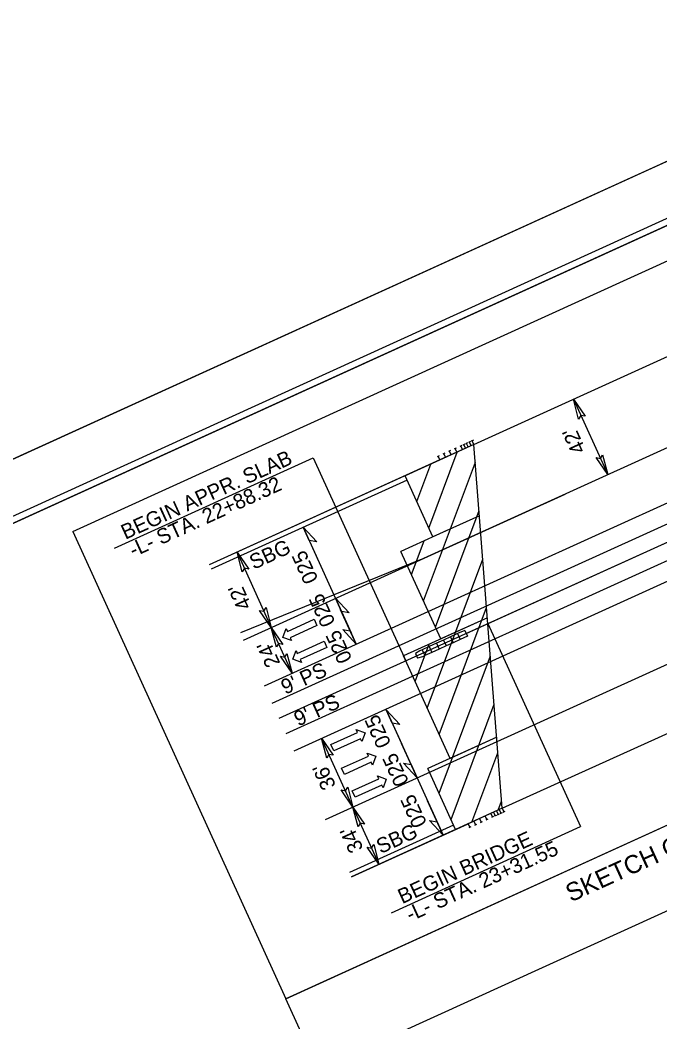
# Model space of a CAD drawing. Extents: x 2247864 to 2249896, y 662531 to 664296.
# Drawn here: x 2248640.5 to 2248887, y 663642.7 to 664028.8 of the extents above; entities that cross this region are included whole.
import ezdxf

# ---------------------------------------------------------------- set-up
doc = ezdxf.new("R2010")
doc.units = 0
for name, color, linetype in [('Prop Approach Slab', 7, 'Continuous'), ('Prop Approach Slab Hatching', 7, 'Continuous'), ('Prop Conc Barrier', 7, 'Continuous'), ('Prop Conc Shoulder Berm Gutter', 7, 'Continuous'), ('Prop Dimension', 7, 'Continuous'), ('Prop Dimension Text', 7, 'Continuous'), ('Prop EOT', 7, 'Continuous'), ('Prop Guardrail', 7, 'Continuous'), ('Prop Guardrail Attenuator CELL', 7, 'Continuous'), ('Prop Horizontal Alignment', 7, 'Continuous'), ('Prop Lane Arrow CELL', 7, 'Continuous'), ('Prop Lane Lines', 7, 'Continuous'), ('Prop Paved Shoulder', 7, 'Continuous'), ('Prop Roadway Bridge', 7, 'Continuous'), ('Prop Structure Anchor Unit CELL', 7, 'Continuous'), ('Prop Superelevation  Arrow CELL', 7, 'Continuous'), ('Prop Superelevation Label', 7, 'Continuous'), ('Prop Terminator CELL', 7, 'Continuous'), ('Sheet Clip Boundary CELL', 7, 'Continuous'), ('Sheet Cutting Line CELL', 7, 'Continuous'), ('Sheet Layout Plan Border', 7, 'Continuous'), ('Sheet Plan CELL', 7, 'Continuous'), ('Sheet Plan Layout CELL', 7, 'Continuous'), ('Sheet Plot Border Inside CELL', 7, 'Continuous'), ('Sheet Plot Border Outside CELL', 7, 'Continuous')]:
    doc.layers.add(name, color=color, linetype=linetype)

msp = doc.modelspace()

# ---------------------------------------------------------------- linework, layer by layer
at = {"layer": 'Prop Approach Slab'}
for p, q in [((2248815.39, 663865.29), (2248788.84, 663853.23)), ((2248799.55, 663829.64), (2248788.84, 663853.23)), ((2248817.52, 663837.8), (2248799.55, 663829.64)), ((2248805.23, 663832.22), (2248787.26, 663824.06)), ((2248802.6, 663790.29), (2248787.26, 663824.06)), ((2248820.57, 663798.45), (2248788.22, 663783.75)), ((2248820.57, 663798.45), (2248802.6, 663790.29)), ((2248806.17, 663744.23), (2248788.22, 663783.75)), ((2248824.14, 663752.39), (2248797.63, 663740.35)), ((2248824.14, 663752.39), (2248806.17, 663744.23)), ((2248808.29, 663716.87), (2248797.63, 663740.35)), ((2248826.26, 663725.03), (2248808.29, 663716.87))]:
    msp.add_line(p, q, dxfattribs=at)
at = {"layer": 'Prop Approach Slab Hatching'}
for p, q in [((2248798, 663833.06), (2248808.94, 663862.32)), ((2248793.38, 663843.23), (2248798.79, 663857.71)), ((2248795.93, 663804.98), (2248815.92, 663858.44)), ((2248800.55, 663794.8), (2248817.37, 663839.77)), ((2248791.31, 663815.15), (2248796.15, 663828.1)), ((2248797.34, 663763.68), (2248818.81, 663821.11)), ((2248801.96, 663753.5), (2248820.26, 663802.44)), ((2248792.72, 663773.85), (2248798.1, 663788.24)), ((2248801.93, 663730.88), (2248821.7, 663783.77)), ((2248806.55, 663720.71), (2248823.15, 663765.11)), ((2248814.62, 663719.74), (2248824.6, 663746.44)), ((2248824.77, 663724.36), (2248826.04, 663727.77))]:
    msp.add_line(p, q, dxfattribs=at)
at = {"layer": 'Prop Conc Barrier'}
msp.add_line((2248812.36, 663792.42), (2249009.02, 663881.76), dxfattribs=at)
at = {"layer": 'Prop Conc Shoulder Berm Gutter'}
for p, q in [((2248789.62, 663851.52), (2248714.17, 663817.24)), ((2248807.53, 663718.55), (2248767.46, 663700.29))]:
    msp.add_line(p, q, dxfattribs=at)
at = {"layer": 'Prop Dimension'}
for p, q in [((2248853.72, 663882.7), (2248866.93, 663853.62)), ((2248724.11, 663823.81), (2248737.32, 663794.73)), ((2248745.34, 663777.06), (2248737.32, 663794.73)), ((2248768.75, 663725.54), (2248756.71, 663752.04)), ((2248768.75, 663725.54), (2248778.78, 663703.46))]:
    msp.add_line(p, q, dxfattribs=at)
at = {"layer": 'Prop Dimension Text'}
for p, q in [((2248660.85, 663831.67), (2249087.72, 664026.19)), ((2248676.93, 663825.24), (2248753.43, 663860.1)), ((2248753.43, 663860.1), (2248789.08, 663781.85)), ((2249169.78, 663846.12), (2248742.91, 663651.6)), ((2248660.85, 663831.67), (2248742.91, 663651.6)), ((2248820.74, 663796.23), (2248856.4, 663717.98)), ((2248783.56, 663684.79), (2248856.4, 663717.98))]:
    msp.add_line(p, q, dxfattribs=at)
msp.add_lwpolyline([(2248742.91, 663651.6), (2249169.78, 663846.12), (2249182.27, 663818.71), (2248755.39, 663624.19)], close=True, dxfattribs=at)
at = {"layer": 'Prop EOT'}
for p, q in [((2248794.68, 663820.8), (2249074.06, 663947.71)), ((2248734.68, 663772.23), (2249082.11, 663930.06)), ((2248746.08, 663747.22), (2249093.51, 663905.04)), ((2248758.15, 663720.73), (2249028.21, 663843.41)), ((2248794.68, 663820.8), (2248725.39, 663792.62))]:
    msp.add_line(p, q, dxfattribs=at)
at = {"layer": 'Prop Guardrail'}
for p, q in [((2248802.26, 663859.28), (2248713.4, 663818.92)), ((2248768.2, 663698.66), (2248813.11, 663719.06))]:
    msp.add_line(p, q, dxfattribs=at)
at = {"layer": 'Prop Guardrail Attenuator CELL'}
for p, q in [((2248806.36, 663791.11), (2248803.63, 663789.87)), ((2248809.09, 663792.35), (2248806.36, 663791.11)), ((2248806.36, 663791.11), (2248807.4, 663788.84)), ((2248810.13, 663790.08), (2248807.4, 663788.84)), ((2248811.82, 663793.6), (2248809.09, 663792.35)), ((2248809.09, 663792.35), (2248810.13, 663790.08)), ((2248812.86, 663791.32), (2248810.13, 663790.08)), ((2248811.82, 663793.6), (2248812.86, 663791.32)), ((2248798.17, 663787.39), (2248795.44, 663786.15)), ((2248800.9, 663788.63), (2248798.17, 663787.39)), ((2248798.17, 663787.39), (2248799.2, 663785.12)), ((2248801.93, 663786.36), (2248799.2, 663785.12)), ((2248803.63, 663789.87), (2248800.9, 663788.63)), ((2248800.9, 663788.63), (2248801.93, 663786.36)), ((2248804.66, 663787.6), (2248801.93, 663786.36)), ((2248803.63, 663789.87), (2248804.66, 663787.6)), ((2248807.4, 663788.84), (2248804.66, 663787.6)), ((2248794.53, 663785.74), (2248792.81, 663784.68)), ((2248792.81, 663784.68), (2248793.22, 663783.77)), ((2248793.22, 663783.77), (2248793.64, 663782.86)), ((2248795.56, 663783.46), (2248793.64, 663782.86)), ((2248795.44, 663786.15), (2248794.53, 663785.74)), ((2248795.44, 663786.15), (2248796.47, 663783.87)), ((2248796.47, 663783.87), (2248795.56, 663783.46)), ((2248799.2, 663785.12), (2248796.47, 663783.87))]:
    msp.add_line(p, q, dxfattribs=at)
at = {"layer": 'Prop Horizontal Alignment'}
msp.add_line((2248740.38, 663759.73), (2249087.81, 663917.55), dxfattribs=at)
at = {"layer": 'Prop Lane Arrow CELL'}
for p, q in [((2248743.5, 663793.18), (2248753.8, 663797.87)), ((2248753.8, 663797.87), (2248754.91, 663795.45)), ((2248741.75, 663790.87), (2248743, 663794.28)), ((2248743, 663794.28), (2248743.5, 663793.18)), ((2248754.91, 663795.45), (2248744.61, 663790.75)), ((2248745.11, 663789.65), (2248741.75, 663790.87)), ((2248744.61, 663790.75), (2248745.11, 663789.65)), ((2248747.34, 663784.76), (2248757.64, 663789.45)), ((2248758.75, 663787.02), (2248748.45, 663782.33)), ((2248757.64, 663789.45), (2248758.75, 663787.02)), ((2248745.59, 663782.45), (2248746.84, 663785.86)), ((2248748.95, 663781.23), (2248745.59, 663782.45)), ((2248746.84, 663785.86), (2248747.34, 663784.76)), ((2248748.45, 663782.33), (2248748.95, 663781.23)), ((2248770.58, 663754.28), (2248770.07, 663755.39)), ((2248770.07, 663755.39), (2248773.43, 663754.16)), ((2248760.28, 663749.59), (2248770.58, 663754.28)), ((2248771.68, 663751.86), (2248761.38, 663747.16)), ((2248772.18, 663750.75), (2248771.68, 663751.86)), ((2248773.43, 663754.16), (2248772.18, 663750.75)), ((2248761.38, 663747.16), (2248760.28, 663749.59)), ((2248764.42, 663740.5), (2248774.72, 663745.19)), ((2248774.72, 663745.19), (2248774.22, 663746.3)), ((2248774.22, 663746.3), (2248777.57, 663745.07)), ((2248777.57, 663745.07), (2248776.33, 663741.66)), ((2248765.52, 663738.07), (2248764.42, 663740.5)), ((2248775.82, 663742.76), (2248765.52, 663738.07)), ((2248776.33, 663741.66), (2248775.82, 663742.76)), ((2248768.47, 663731.75), (2248778.77, 663736.44)), ((2248778.77, 663736.44), (2248778.27, 663737.54)), ((2248778.27, 663737.54), (2248781.62, 663736.32)), ((2248781.62, 663736.32), (2248780.38, 663732.91)), ((2248779.88, 663734.01), (2248769.58, 663729.32)), ((2248780.38, 663732.91), (2248779.88, 663734.01)), ((2248769.58, 663729.32), (2248768.47, 663731.75))]:
    msp.add_line(p, q, dxfattribs=at)
at = {"layer": 'Prop Lane Lines'}
msp.add_line((2248726.63, 663789.89), (2248850.47, 663846.15), dxfattribs=at)
at = {"layer": 'Prop Paved Shoulder'}
for p, q in [((2248737.69, 663765.61), (2249085.12, 663923.43)), ((2248743.07, 663753.84), (2249090.5, 663911.67)), ((2248796.99, 663856.93), (2248713.43, 663818.85)), ((2248808.29, 663716.87), (2248768.22, 663698.61))]:
    msp.add_line(p, q, dxfattribs=at)
at = {"layer": 'Prop Roadway Bridge'}
for p, q in [((2248815.39, 663865.29), (2248995.74, 663947.21)), ((2248826.26, 663725.03), (2248815.39, 663865.29)), ((2248826.26, 663725.03), (2249006.6, 663806.96))]:
    msp.add_line(p, q, dxfattribs=at)
at = {"layer": 'Prop Structure Anchor Unit CELL'}
for p, q in [((2248815.39, 663865.29), (2248802.24, 663859.31)), ((2248808.58, 663863.88), (2248807.78, 663863.52)), ((2248808.82, 663862.3), (2248808.18, 663863.7)), ((2248810.77, 663864.88), (2248809.97, 663864.51)), ((2248811.01, 663863.29), (2248810.37, 663864.7)), ((2248811.87, 663865.38), (2248811.06, 663865.01)), ((2248812.1, 663863.79), (2248811.47, 663865.19)), ((2248812.96, 663865.87), (2248812.16, 663865.51)), ((2248813.2, 663864.29), (2248812.56, 663865.69)), ((2248814.06, 663866.37), (2248813.26, 663866.01)), ((2248814.29, 663864.79), (2248813.66, 663866.19)), ((2248815.15, 663866.87), (2248814.35, 663866.5)), ((2248815.39, 663865.29), (2248814.75, 663866.69)), ((2248802.01, 663860.9), (2248801.21, 663860.53)), ((2248802.24, 663859.31), (2248801.61, 663860.72)), ((2248804.2, 663861.89), (2248803.4, 663861.53)), ((2248804.44, 663860.31), (2248803.8, 663861.71)), ((2248806.39, 663862.89), (2248805.59, 663862.52)), ((2248806.63, 663861.3), (2248805.99, 663862.71)), ((2248826.26, 663725.03), (2248813.11, 663719.06)), ((2248825.16, 663724.53), (2248825.8, 663723.13)), ((2248826.26, 663725.03), (2248826.89, 663723.63)), ((2248817.49, 663721.05), (2248818.13, 663719.65)), ((2248819.68, 663722.05), (2248820.32, 663720.64)), ((2248820.72, 663720.83), (2248819.92, 663720.46)), ((2248821.87, 663723.04), (2248822.51, 663721.64)), ((2248822.91, 663721.82), (2248822.11, 663721.46)), ((2248822.97, 663723.54), (2248823.61, 663722.14)), ((2248824.01, 663722.32), (2248823.2, 663721.95)), ((2248824.06, 663724.04), (2248824.7, 663722.63)), ((2248825.1, 663722.82), (2248824.3, 663722.45)), ((2248826.2, 663723.31), (2248825.4, 663722.95)), ((2248827.29, 663723.81), (2248826.49, 663723.45)), ((2248813.11, 663719.06), (2248813.75, 663717.66)), ((2248814.15, 663717.84), (2248813.35, 663717.48)), ((2248815.3, 663720.06), (2248815.94, 663718.65)), ((2248816.34, 663718.84), (2248815.54, 663718.47)), ((2248818.53, 663719.83), (2248817.73, 663719.47))]:
    msp.add_line(p, q, dxfattribs=at)
at = {"layer": 'Prop Superelevation  Arrow CELL'}
for p, q in [((2248749.61, 663833.33), (2248755.64, 663820.08)), ((2248762.04, 663805.96), (2248768.08, 663792.72)), ((2248770.07, 663788.29), (2248764.03, 663801.54)), ((2248781.6, 663762.98), (2248787.64, 663749.74)), ((2248793.5, 663736.78), (2248787.47, 663750.02)), ((2248803.54, 663714.69), (2248797.5, 663727.94))]:
    msp.add_line(p, q, dxfattribs=at)
for points in [[(2248749.61, 663833.33), (2248754.83, 663827.71), (2248751.94, 663828.22)], [(2248762.04, 663805.96), (2248767.27, 663800.34), (2248764.37, 663800.86)], [(2248770.07, 663788.29), (2248764.84, 663793.91), (2248767.74, 663793.4)], [(2248781.6, 663762.98), (2248786.83, 663757.36), (2248783.93, 663757.88)], [(2248793.5, 663736.78), (2248788.28, 663742.39), (2248791.18, 663741.88)], [(2248803.54, 663714.69), (2248798.31, 663720.31), (2248801.21, 663719.8)]]:
    msp.add_lwpolyline(points, close=True, dxfattribs=at)
at = {"layer": 'Prop Superelevation Label'}
for p, q in [((2248749.61, 663833.33), (2248770.07, 663788.29)), ((2248781.6, 663762.98), (2248803.54, 663714.69))]:
    msp.add_line(p, q, dxfattribs=at)
at = {"layer": 'Prop Terminator CELL'}
for points in [[(2248855.72, 663875.04), (2248853.72, 663882.7), (2248858.22, 663876.13), (2248856.55, 663876.47)], [(2248864.92, 663861.27), (2248866.93, 663853.62), (2248862.42, 663860.18), (2248864.09, 663859.85)], [(2248726.11, 663816.15), (2248724.11, 663823.81), (2248728.62, 663817.24), (2248726.94, 663817.57)], [(2248735.32, 663802.38), (2248737.32, 663794.73), (2248732.82, 663801.29), (2248734.49, 663800.96)], [(2248739.32, 663787.08), (2248737.32, 663794.73), (2248741.82, 663788.16), (2248740.15, 663788.5)], [(2248743.34, 663784.72), (2248745.34, 663777.06), (2248740.84, 663783.63), (2248742.51, 663783.29)], [(2248758.71, 663744.39), (2248756.71, 663752.04), (2248761.21, 663745.48), (2248759.54, 663745.81)], [(2248766.75, 663733.2), (2248768.75, 663725.54), (2248764.24, 663732.11), (2248765.92, 663731.77)], [(2248770.75, 663717.89), (2248768.75, 663725.54), (2248773.25, 663718.98), (2248771.58, 663719.31)], [(2248776.78, 663711.11), (2248778.78, 663703.46), (2248774.27, 663710.02), (2248775.95, 663709.69)]]:
    msp.add_lwpolyline(points, close=True, dxfattribs=at)
at = {"layer": 'Sheet Clip Boundary CELL'}
msp.add_lwpolyline([(2248241.67, 663371.06), (2248514.44, 662770.57), (2248551.22, 662641.58), (2249564.56, 663103.35), (2249531.17, 663176.64), (2249788.88, 663294.08), (2249780.68, 663312.06), (2249743.43, 663294.89), (2249677.44, 663353.62), (2249425.27, 663908.72), (2249477.5, 663985.14), (2249305.27, 663906.66), (2249217.58, 664099.11), (2248115.83, 663597.06)], close=True, dxfattribs=at)
at = {"layer": 'Sheet Cutting Line CELL'}
msp.add_line((2249441.45, 664225.83), (2247909.5, 663527.75), dxfattribs=at)
at = {"layer": 'Sheet Layout Plan Border'}
msp.add_lwpolyline([(2248198.13, 663481.51), (2248575.77, 662652.77), (2249849.75, 663233.3), (2249502.05, 663996.33), (2249329.83, 663917.85), (2249242.13, 664110.3), (2248140.38, 663608.25)], close=True, dxfattribs=at)
at = {"layer": 'Sheet Plan CELL'}
for points in [[(2249435.32, 664198.33), (2248070.33, 663576.33), (2248505.72, 662620.85), (2249870.7, 663242.85)], [(2248505.72, 662620.85), (2248070.31, 663576.29), (2249253.26, 664115.38), (2249315.49, 663978.83), (2249497.53, 664061.77), (2249870.7, 663242.85)]]:
    msp.add_lwpolyline(points, close=True, dxfattribs=at)
at = {"layer": 'Sheet Plan Layout CELL'}
msp.add_lwpolyline([(2248070.31, 663576.29), (2248505.72, 662620.85), (2249870.68, 663242.84), (2249522.99, 664005.87), (2249305.27, 663906.66), (2249217.58, 664099.11)], close=True, dxfattribs=at)
at = {"layer": 'Sheet Plot Border Inside CELL'}
msp.add_lwpolyline([(2248367.09, 662554.92), (2249883.1, 663245.75), (2249445.65, 664205.77), (2247929.62, 663514.94)], close=True, dxfattribs=at)
at = {"layer": 'Sheet Plot Border Outside CELL'}
msp.add_lwpolyline([(2248363.56, 662531.33), (2249895.5, 663229.41), (2249441.45, 664225.83), (2247909.5, 663527.75)], close=True, dxfattribs=at)

# ---------------------------------------------------------------- texts
at = {"layer": 'Prop Dimension Text'}
for s, height, rotation, p in [("42'", 5.775, 114.4301, (2248858.59, 663863.2)), ('BEGIN APPR. SLAB', 5.775, 24.4979, (2248681.1, 663828.51)), ('-L- STA. 22+88.32', 5.775, 24.4979, (2248684.21, 663821.68)), ('SBG', 5.775, 24.4979, (2248730.55, 663816.93)), ("42'", 5.775, 114.4301, (2248729.87, 663802.99)), ("24'", 5.775, 114.4301, (2248740.88, 663780.95)), ('SKETCH OF BRIDGE IN RELATION TO ROADWAY', 7, 24.4979, (2248852.72, 663688.74)), ("9' PS", 5.775, 24.4301, (2248742.71, 663768.78)), ("9' PS", 5.775, 24.4301, (2248747.7, 663756.51)), ("36'", 5.775, 114.4301, (2248762.35, 663733.74)), ('SBG', 5.775, 24.4979, (2248779.44, 663707.39)), ("34'", 5.775, 114.4301, (2248772.91, 663709.49)), ('BEGIN BRIDGE', 5.775, 24.4979, (2248787.73, 663688.07)), ('-L- STA. 23+31.55', 5.775, 24.4979, (2248790.84, 663681.24))]:
    msp.add_text(s, height=height, rotation=rotation, dxfattribs=at).set_placement(p)
at = {"layer": 'Prop Superelevation Label'}
for p in [(2248755.54, 663813.23), (2248762.14, 663796.63), (2248768.61, 663782.55), (2248783.61, 663749.96), (2248790.47, 663735.16), (2248797.41, 663719.23)]:
    msp.add_text('025', height=5.775, rotation=114.4979, dxfattribs=at).set_placement(p)

doc.saveas('drawing.dxf')
